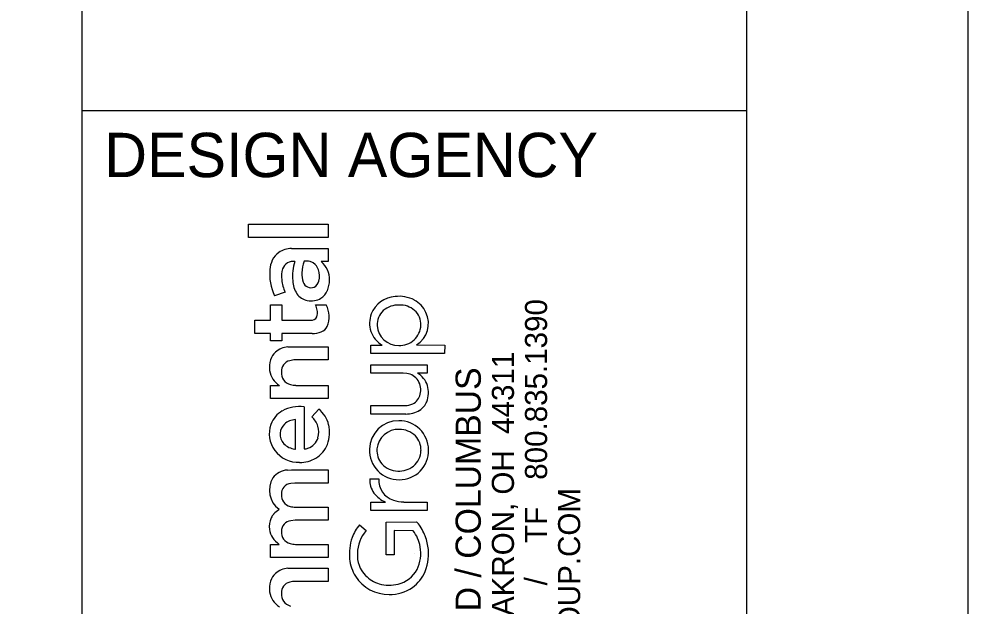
# Model space of a CAD drawing. Extents: x -0.3 to 34, y 0 to 22.
# Drawn here: x 31.857 to 34, y 3.382 to 4.707 of the extents above; entities that cross this region are included whole.
import ezdxf

# ---------------------------------------------------------------- set-up
doc = ezdxf.new("R2010")
doc.units = 0
for name, color, linetype in [('PM_X_CL_Double_Solid', 7, 'Continuous'), ('PM_X_CL_Pass_Proh_Lt', 7, 'Continuous'), ('PV_X_EOP', 7, 'Continuous')]:
    doc.layers.add(name, color=color, linetype=linetype)

msp = doc.modelspace()

# ---------------------------------------------------------------- linework, layer by layer
at = {"layer": 'PM_X_CL_Double_Solid'}
msp.add_lwpolyline([(0, 0), (34, 0), (34, 22), (0, 22)], close=True, dxfattribs=at)
at = {"layer": 'PM_X_CL_Pass_Proh_Lt'}
for p, q in [((32, 0.5), (32, 21.5)), ((32, 4.5), (33.5, 4.5))]:
    msp.add_line(p, q, dxfattribs=at)
msp.add_lwpolyline([(1.5, 21.5), (33.5, 21.5), (33.5, 0.5), (1.5, 0.5)], close=True, dxfattribs=at)
at = {"layer": 'PV_X_EOP'}
for p, q in [((32.3756, 4.2141), (32.3756, 4.244)), ((32.3756, 4.244), (32.5557, 4.244)), ((32.5557, 4.244), (32.5557, 4.2141)), ((32.5557, 4.2141), (32.3756, 4.2141)), ((32.4727, 4.189), (32.5555, 4.1892)), ((32.5555, 4.1892), (32.5557, 4.1596)), ((32.5557, 4.1596), (32.5397, 4.1596)), ((32.4582, 4.0904), (32.4343, 4.0823)), ((32.4254, 4.027), (32.4255, 4.0621)), ((32.4255, 4.0621), (32.4511, 4.0621)), ((32.4511, 4.0621), (32.4512, 4.027)), ((32.527, 4.0616), (32.5511, 4.0616)), ((32.3896, 3.9972), (32.3896, 4.027)), ((32.3896, 4.027), (32.4254, 4.027)), ((32.4512, 4.027), (32.515, 4.027)), ((32.515, 4.027), (32.52, 4.0275)), ((32.4254, 3.9972), (32.3896, 3.9972)), ((32.4254, 3.9807), (32.4254, 3.9972)), ((32.5197, 3.9972), (32.4511, 3.9972)), ((32.4511, 3.9972), (32.4511, 3.9807)), ((32.4511, 3.9807), (32.4254, 3.9807)), ((32.4644, 3.9669), (32.4729, 3.9673)), ((32.4729, 3.9673), (32.5557, 3.9673)), ((32.5557, 3.9673), (32.5557, 3.9375)), ((32.6515, 3.9521), (32.6515, 3.9711)), ((32.6515, 3.9711), (32.6771, 3.9711)), ((32.7549, 3.9713), (32.8186, 3.9711)), ((32.8186, 3.9711), (32.8184, 3.9521)), ((32.8184, 3.9521), (32.6515, 3.9521)), ((32.5557, 3.9375), (32.4814, 3.9375)), ((32.6515, 3.908), (32.6515, 3.9267)), ((32.6515, 3.9267), (32.7791, 3.9266)), ((32.7791, 3.9266), (32.7791, 3.908)), ((32.7249, 3.908), (32.6515, 3.908)), ((32.7328, 3.9073), (32.7249, 3.908)), ((32.7791, 3.908), (32.7569, 3.908)), ((32.4254, 3.8503), (32.4254, 3.8802)), ((32.4254, 3.8802), (32.4455, 3.8802)), ((32.4822, 3.8802), (32.5557, 3.8802)), ((32.5557, 3.8802), (32.5557, 3.8504)), ((32.5557, 3.8504), (32.4254, 3.8503)), ((32.5011, 3.8321), (32.5012, 3.7366)), ((32.5188, 3.8093), (32.5342, 3.8266)), ((32.6515, 3.8344), (32.7291, 3.8345)), ((32.6517, 3.8154), (32.6515, 3.8344)), ((32.7307, 3.8154), (32.6517, 3.8154)), ((32.4814, 3.7364), (32.4814, 3.803)), ((32.4802, 3.7363), (32.4814, 3.7364)), ((32.4633, 3.6891), (32.4726, 3.6897)), ((32.4726, 3.6897), (32.5556, 3.6897)), ((32.5556, 3.6897), (32.5557, 3.6598)), ((32.6493, 3.6691), (32.6698, 3.6691)), ((32.4806, 3.6598), (32.471, 3.6588)), ((32.5557, 3.6598), (32.4806, 3.6598)), ((32.4444, 3.5992), (32.4446, 3.6007)), ((32.4822, 3.6055), (32.5557, 3.6055)), ((32.5557, 3.6055), (32.5557, 3.5757)), ((32.6515, 3.598), (32.6515, 3.617)), ((32.6515, 3.617), (32.6848, 3.617)), ((32.726, 3.617), (32.7791, 3.617)), ((32.7791, 3.617), (32.779, 3.598)), ((32.779, 3.598), (32.6515, 3.598)), ((32.4809, 3.5757), (32.4714, 3.5747)), ((32.5557, 3.5757), (32.4809, 3.5757)), ((32.6264, 3.5655), (32.6411, 3.5524)), ((32.6868, 3.5718), (32.7552, 3.5719)), ((32.6868, 3.4978), (32.6868, 3.5718)), ((32.7045, 3.5524), (32.7043, 3.4978)), ((32.7474, 3.5523), (32.7045, 3.5524)), ((32.4254, 3.4915), (32.4254, 3.5214)), ((32.4254, 3.5214), (32.4451, 3.5214)), ((32.4821, 3.5214), (32.5557, 3.5214)), ((32.5557, 3.5214), (32.5557, 3.4916)), ((32.7043, 3.4978), (32.6868, 3.4978)), ((32.75, 3.5), (32.75, 3.5)), ((32.5557, 3.4916), (32.4254, 3.4915)), ((32.4644, 3.4674), (32.4729, 3.4678)), ((32.4729, 3.4678), (32.5557, 3.4678)), ((32.5557, 3.4678), (32.5557, 3.438)), ((32.5557, 3.438), (32.4814, 3.438))]:
    msp.add_line(p, q, dxfattribs=at)
msp.add_lwpolyline([(32.3756, 4.2141), (32.3756, 4.244), (32.5557, 4.244), (32.5557, 4.2141)], close=True, dxfattribs=at)
for points in [[(32.4727, 4.189), (32.5555, 4.1892), (32.5557, 4.1596)], [(32.5557, 4.1596), (32.5397, 4.1596)], [(32.4582, 4.0904), (32.4343, 4.0823)], [(32.5197, 3.9972), (32.4511, 3.9972), (32.4511, 3.9807), (32.4254, 3.9807), (32.4254, 3.9972), (32.3896, 3.9972), (32.3896, 4.027), (32.4254, 4.027), (32.4255, 4.0621), (32.4511, 4.0621), (32.4512, 4.027), (32.515, 4.027), (32.52, 4.0275)], [(32.527, 4.0616), (32.5511, 4.0616)], [(32.4644, 3.9669), (32.4729, 3.9673), (32.5557, 3.9673), (32.5557, 3.9375), (32.4814, 3.9375)], [(32.7549, 3.9713), (32.8186, 3.9711), (32.8184, 3.9521), (32.6515, 3.9521)], [(32.6515, 3.9521), (32.6515, 3.9711), (32.6771, 3.9711)], [(32.7328, 3.9073), (32.7249, 3.908), (32.6515, 3.908), (32.6515, 3.9267), (32.7791, 3.9266), (32.7791, 3.908), (32.7569, 3.908)], [(32.4254, 3.8503), (32.4254, 3.8802), (32.4455, 3.8802)], [(32.4822, 3.8802), (32.5557, 3.8802), (32.5557, 3.8504), (32.4254, 3.8503)], [(32.5011, 3.8321), (32.5012, 3.7366)], [(32.5188, 3.8093), (32.5342, 3.8266)], [(32.7307, 3.8154), (32.6517, 3.8154), (32.6515, 3.8344), (32.7291, 3.8345)], [(32.4802, 3.7363), (32.4814, 3.7364), (32.4814, 3.803)], [(32.4633, 3.6891), (32.4726, 3.6897), (32.5556, 3.6897), (32.5557, 3.6598), (32.4806, 3.6598), (32.471, 3.6588)], [(32.6493, 3.6691), (32.6698, 3.6691)], [(32.4444, 3.5992), (32.4446, 3.6007)], [(32.4822, 3.6055), (32.5557, 3.6055), (32.5557, 3.5757), (32.4809, 3.5757), (32.4714, 3.5747)], [(32.6515, 3.598), (32.6515, 3.617), (32.6848, 3.617)], [(32.726, 3.617), (32.7791, 3.617), (32.779, 3.598), (32.6515, 3.598)], [(32.6264, 3.5655), (32.6411, 3.5524)], [(32.7474, 3.5523), (32.7045, 3.5524), (32.7043, 3.4978), (32.6868, 3.4978), (32.6868, 3.5718), (32.7552, 3.5719)], [(32.4254, 3.4915), (32.4254, 3.5214), (32.4451, 3.5214)], [(32.4821, 3.5214), (32.5557, 3.5214), (32.5557, 3.4916), (32.4254, 3.4915)], [(32.4644, 3.4674), (32.4729, 3.4678), (32.5557, 3.4678), (32.5557, 3.438), (32.4814, 3.438)]]:
    msp.add_lwpolyline(points, dxfattribs=at)
for centre, radius, start, end in [((32.4685, 4.1447), 0.043, 124.537, 155.6594), ((32.4685, 4.1447), 0.043, 124.537, 155.6594), ((32.4745, 4.1326), 0.0565, 91.8942, 122.6317), ((32.4745, 4.1326), 0.0565, 91.8942, 122.6317), ((32.4882, 4.1361), 0.0646, 155.9764, 175.3149), ((32.4882, 4.1361), 0.0646, 155.9764, 175.3149), ((32.4753, 4.1356), 0.024, 119.4252, 161.6629), ((32.4753, 4.1356), 0.024, 119.4252, 161.6629), ((32.4779, 4.1278), 0.0321, 85.3802, 116.6222), ((32.4779, 4.1278), 0.0321, 85.3802, 116.6222), ((32.5879, 4.1251), 0.1129, 162.0821, 184.5285), ((32.5879, 4.1251), 0.1129, 162.0821, 184.5285), ((32.5801, 4.1313), 0.0841, 159.8366, 178.0362), ((32.5801, 4.1313), 0.0841, 159.8366, 178.0362), ((32.5051, 4.1074), 0.053, 79.6696, 94.2322), ((32.5051, 4.1074), 0.053, 79.6696, 94.2322), ((32.5089, 4.1364), 0.0238, 56.8913, 76.2149), ((32.5089, 4.1364), 0.0238, 56.8913, 76.2149), ((32.5055, 4.1191), 0.0529, 358.0746, 49.762), ((32.5055, 4.1191), 0.0529, 358.0746, 49.762), ((32.5364, 4.1308), 0.113, 174.6101, 205.3899), ((32.5364, 4.1308), 0.113, 174.6101, 205.3899), ((32.5076, 4.1265), 0.0576, 163.1369, 188.1675), ((32.5076, 4.1265), 0.0576, 163.1369, 188.1675), ((32.5052, 4.1318), 0.0297, 17.5984, 55.7282), ((32.5052, 4.1318), 0.0297, 17.5984, 55.7282), ((32.4916, 4.1264), 0.0443, 345.9408, 18.9919), ((32.4916, 4.1264), 0.0443, 345.9408, 18.9919), ((32.5473, 4.1297), 0.0973, 186.7598, 203.7981), ((32.5473, 4.1297), 0.0973, 186.7598, 203.7981), ((32.5328, 4.1187), 0.0575, 182.5676, 213.7144), ((32.5328, 4.1187), 0.0575, 182.5676, 213.7144), ((32.5466, 4.1303), 0.0506, 175.5903, 199.8857), ((32.5466, 4.1303), 0.0506, 175.5903, 199.8857), ((32.5152, 4.1199), 0.0199, 295.2883, 347.4639), ((32.5152, 4.1199), 0.0199, 295.2883, 347.4639), ((32.5019, 4.1168), 0.0566, 336.016, 0.5951), ((32.5019, 4.1168), 0.0566, 336.016, 0.5951), ((32.5164, 4.1189), 0.0184, 198.2844, 293.3081), ((32.5164, 4.1189), 0.0184, 198.2844, 293.3081), ((32.5175, 4.1097), 0.0394, 303.4436, 336.18), ((32.5175, 4.1097), 0.0394, 303.4436, 336.18), ((32.5149, 4.1078), 0.0366, 215.0668, 259.8133), ((32.5149, 4.1078), 0.0366, 215.0668, 259.8133), ((32.5175, 4.1131), 0.0423, 257.5256, 300.882), ((32.5175, 4.1131), 0.0423, 257.5256, 300.882), ((32.7108, 4.0182), 0.0624, 93.9866, 158.3119), ((32.7108, 4.0182), 0.0624, 93.9866, 158.3119), ((32.7156, 4.0065), 0.0746, 62.6889, 97.0135), ((32.7156, 4.0065), 0.0746, 62.6889, 97.0135), ((32.7212, 4.0191), 0.0608, 25.0657, 61.9602), ((32.7212, 4.0191), 0.0608, 25.0657, 61.9602), ((32.4863, 4.042), 0.0452, 10.1545, 25.723), ((32.4863, 4.042), 0.0452, 10.1545, 25.723), ((32.4957, 4.0436), 0.0356, 351.914, 10.2059), ((32.4957, 4.0436), 0.0356, 351.914, 10.2059), ((32.503, 4.0351), 0.0549, 336.589, 28.8991), ((32.503, 4.0351), 0.0549, 336.589, 28.8991), ((32.7138, 4.0102), 0.0513, 87.8965, 131.1812), ((32.7138, 4.0102), 0.0513, 87.8965, 131.1812), ((32.7175, 4.0102), 0.0513, 49.9089, 92.0363), ((32.7175, 4.0102), 0.0513, 49.9089, 92.0363), ((32.7215, 4.0173), 0.0433, 358.0487, 47.9447), ((32.7215, 4.0173), 0.0433, 358.0487, 47.9447), ((32.5184, 4.04), 0.0126, 277.6142, 353.7918), ((32.5184, 4.04), 0.0126, 277.6142, 353.7918), ((32.707, 4.0202), 0.0581, 158.656, 198.171), ((32.707, 4.0202), 0.0581, 158.656, 198.171), ((32.7092, 4.0167), 0.0434, 132.3289, 182.0949), ((32.7092, 4.0167), 0.0434, 132.3289, 182.0949), ((32.7245, 4.02), 0.0574, 301.9776, 25.6418), ((32.7245, 4.02), 0.0574, 301.9776, 25.6418), ((32.5291, 4.0261), 0.0275, 292.6889, 332.0598), ((32.5291, 4.0261), 0.0275, 292.6889, 332.0598), ((32.7135, 4.0181), 0.0478, 183.5974, 271.7045), ((32.7135, 4.0181), 0.0478, 183.5974, 271.7045), ((32.7172, 4.018), 0.0477, 267.3149, 357.4019), ((32.7172, 4.018), 0.0477, 267.3149, 357.4019), ((32.5209, 4.0486), 0.0514, 268.6727, 291.5235), ((32.5209, 4.0486), 0.0514, 268.6727, 291.5235), ((32.7103, 4.0243), 0.0627, 200.8399, 238.0162), ((32.7103, 4.0243), 0.0627, 200.8399, 238.0162), ((32.4687, 3.9172), 0.0499, 94.9706, 130.2248), ((32.4687, 3.9172), 0.0499, 94.9706, 130.2248), ((32.4635, 3.9255), 0.0402, 132.2238, 161.6823), ((32.4635, 3.9255), 0.0402, 132.2238, 161.6823), ((32.4787, 3.9211), 0.056, 162.274, 187.7917), ((32.4787, 3.9211), 0.056, 162.274, 187.7917), ((32.4748, 3.9116), 0.025, 103.6868, 182.214), ((32.4748, 3.9116), 0.025, 103.6868, 182.214), ((32.4811, 3.8915), 0.046, 89.6051, 105.3303), ((32.4811, 3.8915), 0.046, 89.6051, 105.3303), ((32.4703, 3.9209), 0.0476, 188.9646, 238.6987), ((32.4703, 3.9209), 0.0476, 188.9646, 238.6987), ((32.4774, 3.9085), 0.0276, 175.5844, 255.1382), ((32.4774, 3.9085), 0.0276, 175.5844, 255.1382), ((32.7271, 3.87), 0.0377, 33.5008, 81.3295), ((32.7271, 3.87), 0.0377, 33.5008, 81.3295), ((32.7324, 3.8648), 0.0496, 17.6221, 60.3897), ((32.7324, 3.8648), 0.0496, 17.6221, 60.3897), ((32.4818, 3.9224), 0.0421, 254.0891, 270.5284), ((32.4818, 3.9224), 0.0421, 254.0891, 270.5284), ((32.7241, 3.8695), 0.0405, 346.5618, 31.7539), ((32.7241, 3.8695), 0.0405, 346.5618, 31.7539), ((32.7234, 3.8641), 0.0584, 339.162, 15.6148), ((32.7234, 3.8641), 0.0584, 339.162, 15.6148), ((32.7337, 3.8662), 0.0304, 294.6321, 348.4863), ((32.7337, 3.8662), 0.0304, 294.6321, 348.4863), ((32.7275, 3.8808), 0.0463, 271.952, 294.0894), ((32.7275, 3.8808), 0.0463, 271.952, 294.0894), ((32.739, 3.859), 0.042, 303.1039, 338.1561), ((32.739, 3.859), 0.042, 303.1039, 338.1561), ((32.4789, 3.7737), 0.0558, 118.8294, 160.6224), ((32.4789, 3.7737), 0.0558, 118.8294, 160.6224), ((32.4918, 3.7487), 0.0839, 83.6212, 118.2845), ((32.4918, 3.7487), 0.0839, 83.6212, 118.2845), ((32.494, 3.7763), 0.0644, 13.5328, 51.3627), ((32.494, 3.7763), 0.0644, 13.5328, 51.3627), ((32.7321, 3.8726), 0.0571, 268.627, 301.4778), ((32.7321, 3.8726), 0.0571, 268.627, 301.4778), ((32.477, 3.7709), 0.0298, 132.9855, 177.1802), ((32.477, 3.7709), 0.0298, 132.9855, 177.1802), ((32.4844, 3.7607), 0.0424, 94.0131, 130.8806), ((32.4844, 3.7607), 0.0424, 94.0131, 130.8806), ((32.4803, 3.7702), 0.0549, 19.0387, 45.4432), ((32.4803, 3.7702), 0.0549, 19.0387, 45.4432), ((32.7143, 3.7348), 0.0655, 89.4821, 178.7775), ((32.7143, 3.7348), 0.0655, 89.4821, 178.7775), ((32.7158, 3.7341), 0.0662, 0.4227, 90.7613), ((32.7158, 3.7341), 0.0662, 0.4227, 90.7613), ((32.487, 3.7707), 0.0644, 160.5214, 215.7815), ((32.487, 3.7707), 0.0644, 160.5214, 215.7815), ((32.4782, 3.7697), 0.0311, 175.0014, 223.2876), ((32.4782, 3.7697), 0.0311, 175.0014, 223.2876), ((32.4872, 3.7743), 0.047, 344.6072, 17.0067), ((32.4872, 3.7743), 0.047, 344.6072, 17.0067), ((32.4829, 3.7738), 0.0758, 339.3543, 13.3771), ((32.4829, 3.7738), 0.0758, 339.3543, 13.3771), ((32.714, 3.7324), 0.0485, 87.6883, 175.017), ((32.714, 3.7324), 0.0485, 87.6883, 175.017), ((32.7166, 3.7304), 0.0505, 44.912, 90.7591), ((32.7166, 3.7304), 0.0505, 44.912, 90.7591), ((32.499, 3.7718), 0.035, 288.0108, 343.5536), ((32.499, 3.7718), 0.035, 288.0108, 343.5536), ((32.7196, 3.7345), 0.0455, 358.3228, 43.8349), ((32.7196, 3.7345), 0.0455, 358.3228, 43.8349), ((32.4891, 3.7752), 0.0687, 217.7434, 271.6561), ((32.4891, 3.7752), 0.0687, 217.7434, 271.6561), ((32.4855, 3.7783), 0.0423, 225.0645, 262.797), ((32.4855, 3.7783), 0.0423, 225.0645, 262.797), ((32.5013, 3.7568), 0.0202, 269.7004, 294.8729), ((32.5013, 3.7568), 0.0202, 269.7004, 294.8729), ((32.4955, 3.7698), 0.0626, 300.9439, 338.7322), ((32.4955, 3.7698), 0.0626, 300.9439, 338.7322), ((32.7148, 3.7334), 0.0661, 177.5373, 270.9452), ((32.7148, 3.7334), 0.0661, 177.5373, 270.9452), ((32.7108, 3.7331), 0.0453, 175.5147, 221.4205), ((32.7108, 3.7331), 0.0453, 175.5147, 221.4205), ((32.7167, 3.7327), 0.0654, 269.3083, 1.6791), ((32.7167, 3.7327), 0.0654, 269.3083, 1.6791), ((32.7193, 3.7337), 0.0457, 308.9038, 359.3095), ((32.7193, 3.7337), 0.0457, 308.9038, 359.3095), ((32.492, 3.777), 0.0706, 269.2053, 300.3357), ((32.492, 3.777), 0.0706, 269.2053, 300.3357), ((32.4664, 3.644), 0.0452, 93.9112, 142.3072), ((32.4664, 3.644), 0.0452, 93.9112, 142.3072), ((32.714, 3.7373), 0.0505, 222.6626, 268.3733), ((32.714, 3.7373), 0.0505, 222.6626, 268.3733), ((32.7157, 3.7386), 0.0518, 266.5531, 308.6725), ((32.7157, 3.7386), 0.0518, 266.5531, 308.6725), ((32.4759, 3.6437), 0.0532, 148.2879, 233.9556), ((32.4759, 3.6437), 0.0532, 148.2879, 233.9556), ((32.6988, 3.6666), 0.0495, 177.1621, 216.2802), ((32.6988, 3.6666), 0.0495, 177.1621, 216.2802), ((32.7173, 3.6664), 0.0476, 176.7699, 252.1504), ((32.7173, 3.6664), 0.0476, 176.7699, 252.1504), ((32.4738, 3.635), 0.024, 96.7576, 181.6251), ((32.4738, 3.635), 0.024, 96.7576, 181.6251), ((32.4758, 3.6324), 0.026, 175.8157, 256.1672), ((32.4758, 3.6324), 0.026, 175.8157, 256.1672), ((32.7098, 3.6755), 0.0637, 216.9153, 246.8862), ((32.7098, 3.6755), 0.0637, 216.9153, 246.8862), ((32.7269, 3.6917), 0.0747, 251.1388, 269.3469), ((32.7269, 3.6917), 0.0747, 251.1388, 269.3469), ((32.4817, 3.6505), 0.045, 254.3463, 270.6103), ((32.4817, 3.6505), 0.045, 254.3463, 270.6103), ((32.4714, 3.5612), 0.0488, 156.0638, 187.3493), ((32.4714, 3.5612), 0.0488, 156.0638, 187.3493), ((32.4619, 3.5645), 0.0387, 139.5245, 154.847), ((32.4619, 3.5645), 0.0387, 139.5245, 154.847), ((32.4638, 3.5627), 0.0414, 117.9163, 139.243), ((32.4638, 3.5627), 0.0414, 117.9163, 139.243), ((32.4742, 3.5506), 0.0243, 96.5532, 179.949), ((32.4742, 3.5506), 0.0243, 96.5532, 179.949), ((32.7016, 3.5019), 0.0986, 139.7948, 159.137), ((32.7016, 3.5019), 0.0986, 139.7948, 159.137), ((32.725, 3.5394), 0.0444, 30.9891, 47.161), ((32.725, 3.5394), 0.0444, 30.9891, 47.161), ((32.6709, 3.5002), 0.1111, 25.3031, 33.9618), ((32.6709, 3.5002), 0.1111, 25.3031, 33.9618), ((32.4646, 3.5597), 0.0418, 186.5579, 213.3885), ((32.4646, 3.5597), 0.0418, 186.5579, 213.3885), ((32.4789, 3.5708), 0.0598, 214.7043, 235.6872), ((32.4789, 3.5708), 0.0598, 214.7043, 235.6872), ((32.4761, 3.5486), 0.0263, 175.722, 255.7863), ((32.4761, 3.5486), 0.0263, 175.722, 255.7863), ((32.7187, 3.4997), 0.1154, 161.1438, 185.6281), ((32.7187, 3.4997), 0.1154, 161.1438, 185.6281), ((32.699, 3.5008), 0.0775, 138.258, 179.7006), ((32.699, 3.5008), 0.0775, 138.258, 179.7006), ((32.6789, 3.501), 0.0856, 10.0751, 36.8319), ((32.6789, 3.501), 0.0856, 10.0751, 36.8319), ((32.6704, 3.4999), 0.1117, 8.8034, 25.3348), ((32.6704, 3.4999), 0.1117, 8.8034, 25.3348), ((32.4819, 3.5652), 0.0438, 253.6672, 270.1498), ((32.4819, 3.5652), 0.0438, 253.6672, 270.1498), ((32.6842, 3.5006), 0.0804, 333.4669, 11.0367), ((32.6842, 3.5006), 0.0804, 333.4669, 11.0367), ((32.6756, 3.4998), 0.1065, 338.2887, 9.2855), ((32.6756, 3.4998), 0.1065, 338.2887, 9.2855), ((32.6881, 3.4973), 0.0668, 176.6658, 223.6912), ((32.6881, 3.4973), 0.0668, 176.6658, 223.6912), ((32.6934, 3.497), 0.0899, 185.5077, 212.0129), ((32.6934, 3.497), 0.0899, 185.5077, 212.0129), ((32.4635, 3.426), 0.0402, 132.2238, 161.6823), ((32.4635, 3.426), 0.0402, 132.2238, 161.6823), ((32.4687, 3.4177), 0.0499, 94.9706, 130.2248), ((32.4687, 3.4177), 0.0499, 94.9706, 130.2248), ((32.6905, 3.5001), 0.0704, 224.0215, 253.88), ((32.6905, 3.5001), 0.0704, 224.0215, 253.88), ((32.6987, 3.4955), 0.0652, 282.8815, 331.8147), ((32.6987, 3.4955), 0.0652, 282.8815, 331.8147), ((32.6984, 3.4917), 0.0824, 305.0306, 337.6757), ((32.6984, 3.4917), 0.0824, 305.0306, 337.6757), ((32.4787, 3.4216), 0.056, 162.274, 187.7917), ((32.4787, 3.4216), 0.056, 162.274, 187.7917), ((32.4748, 3.4121), 0.025, 103.6868, 182.214), ((32.4748, 3.4121), 0.025, 103.6868, 182.214), ((32.4811, 3.392), 0.046, 89.6051, 105.3303), ((32.4811, 3.392), 0.046, 89.6051, 105.3303), ((32.6921, 3.4975), 0.0891, 212.7022, 270.714), ((32.6921, 3.4975), 0.0891, 212.7022, 270.714), ((32.6932, 3.5125), 0.0831, 254.4535, 283.9512), ((32.6932, 3.5125), 0.0831, 254.4535, 283.9512), ((32.4703, 3.4214), 0.0476, 188.9646, 238.6987), ((32.4703, 3.4214), 0.0476, 188.9646, 238.6987), ((32.4774, 3.409), 0.0276, 175.5844, 255.1382), ((32.4774, 3.409), 0.0276, 175.5844, 255.1382), ((32.6943, 3.4998), 0.0914, 269.3273, 304.1963), ((32.6943, 3.4998), 0.0914, 269.3273, 304.1963)]:
    msp.add_arc(centre, radius, start, end, dxfattribs=at)

# ---------------------------------------------------------------- texts
msp.add_text('DESIGN AGENCY', height=0.1, dxfattribs=at).set_placement((32.05, 4.35))
for s, height, p in [('800.835.1390', 0.049846, (33.0497, 3.6671)), ('450 GRANT ST., AKRON, OH  44311', 0.049846, (32.9749, 2.8374)), ('AKRON / CLEVELAND / COLUMBUS', 0.056969, (32.9001, 2.638)), ('ENVDESIGNGROUP.COM', 0.049846, (33.1244, 2.8374)), ('TF', 0.04985, (33.0497, 3.5246)), ('/  ', 0.04985, (33.0497, 3.4288))]:
    msp.add_text(s, height=height, rotation=90, dxfattribs=at).set_placement(p)

doc.saveas('drawing.dxf')
